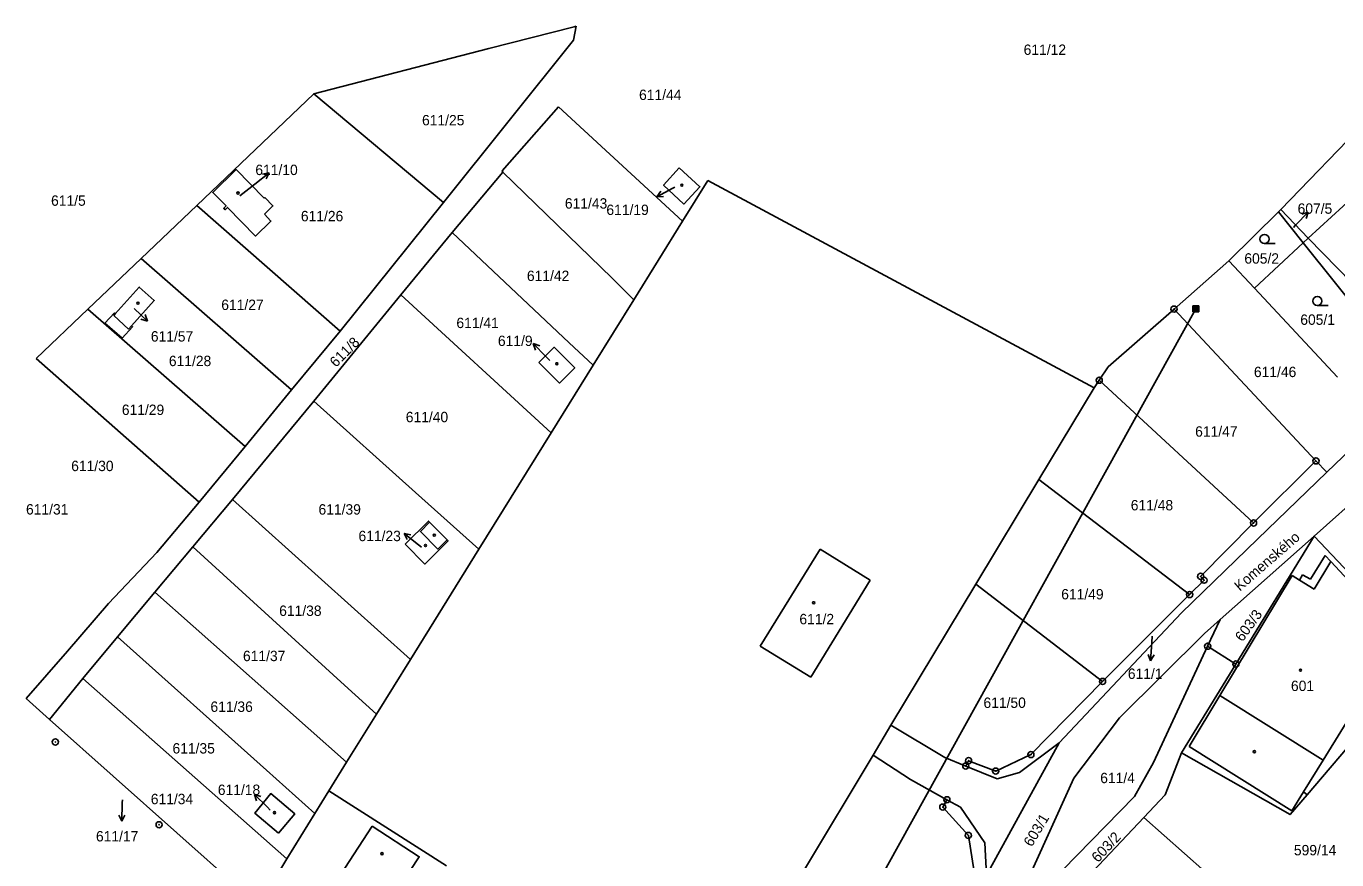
# Model space of a CAD drawing. Extents: x -776701 to -776081, y -974398 to -973771.
# Drawn here: x -776700.9 to -776485.8, y -973908.9 to -973772.2 of the extents above; entities that cross this region are included whole.
import ezdxf

# ---------------------------------------------------------------- set-up
doc = ezdxf.new("R2010")
doc.units = 0
for name, color, linetype in [('Hranice parcel', 7, 'Continuous'), ('Parcelní čísla', 7, 'Continuous'), ('Pop  PČ popisy', 7, 'Continuous'), ('Poz předměty', 7, 'Continuous'), ('Vnitřní kresba', 7, 'Continuous'), ('Značky bodu BP', 7, 'Continuous'), ('Značky budov', 7, 'Continuous'), ('Značky kultur', 7, 'Continuous')]:
    doc.layers.add(name, color=color, linetype=linetype)

msp = doc.modelspace()

# ---------------------------------------------------------------- linework, layer by layer
at = {"layer": 'Hranice parcel'}
for p, q in [((-776624.97, -973775.87), (-776610.98, -973772.28)), ((-776610.98, -973772.28), (-776610.62, -973772.19)), ((-776653.67, -973783.29), (-776624.97, -973775.87)), ((-776672.89, -973801.59), (-776653.67, -973783.29)), ((-776653.67, -973783.29), (-776632.4, -973801.11)), ((-776476.67, -973783.23), (-776495, -973802.25)), ((-776593.17, -973804.15), (-776613.55, -973785.39)), ((-776471.2, -973789.18), (-776490.54, -973806.98)), ((-776630.97, -973806.04), (-776622.69, -973796.12)), ((-776589.04, -973797.5), (-776593.17, -973804.15)), ((-776525.66, -973831.52), (-776589.04, -973797.5)), ((-776682.03, -973810.29), (-776672.89, -973801.59)), ((-776672.89, -973801.59), (-776649.36, -973822.22)), ((-776632.4, -973801.11), (-776649.36, -973822.22)), ((-776495.38, -973802.65), (-776503.53, -973810.68)), ((-776495, -973802.25), (-776495.38, -973802.65)), ((-776491.34, -973807.72), (-776495.38, -973802.65)), ((-776495, -973802.25), (-776490.54, -973806.98)), ((-776639.43, -973816.25), (-776630.97, -973806.04)), ((-776593.17, -973804.15), (-776601.19, -973817.06)), ((-776491.34, -973807.72), (-776499.32, -973815.16)), ((-776490.54, -973806.98), (-776491.34, -973807.72)), ((-776478.83, -973823.4), (-776491.34, -973807.72)), ((-776490.54, -973806.98), (-776476.07, -973821.74)), ((-776690.78, -973818.62), (-776682.03, -973810.29)), ((-776682.03, -973810.29), (-776657.33, -973831.81)), ((-776512.54, -973818.58), (-776503.53, -973810.68)), ((-776503.53, -973810.68), (-776499.32, -973815.16)), ((-776653.69, -973833.69), (-776639.43, -973816.25)), ((-776614.75, -973838.88), (-776639.43, -973816.25)), ((-776499.32, -973815.16), (-776485.7, -973829.75)), ((-776699.26, -973826.69), (-776690.78, -973818.62)), ((-776690.78, -973818.62), (-776664.95, -973841.11)), ((-776601.19, -973817.06), (-776607.86, -973827.79)), ((-776523.35, -973828.07), (-776512.54, -973818.58)), ((-776512.54, -973818.58), (-776489.25, -973843.48)), ((-776649.36, -973822.22), (-776657.33, -973831.81)), ((-776699.26, -973826.69), (-776672.5, -973850.24)), ((-776607.86, -973827.79), (-776614.75, -973838.88)), ((-776524.81, -973830.25), (-776523.35, -973828.07)), ((-776657.33, -973831.81), (-776664.95, -973841.11)), ((-776534.7, -973846.51), (-776525.66, -973831.52)), ((-776525.66, -973831.52), (-776524.81, -973830.25)), ((-776524.81, -973830.25), (-776499.49, -973853.67)), ((-776667.05, -973849.79), (-776653.69, -973833.69)), ((-776478.78, -973836.99), (-776487.44, -973845.34)), ((-776614.75, -973838.88), (-776626.61, -973857.96)), ((-776664.95, -973841.11), (-776672.5, -973850.24)), ((-776489.25, -973843.48), (-776499.49, -973853.67)), ((-776487.44, -973845.34), (-776489.25, -973843.48)), ((-776545.07, -973863.71), (-776534.7, -973846.51)), ((-776534.7, -973846.51), (-776509.98, -973865.41)), ((-776487.44, -973845.34), (-776498.85, -973856.35)), ((-776489.54, -973855.85), (-776477.68, -973845.24)), ((-776672.5, -973850.24), (-776679.43, -973858.51)), ((-776673.56, -973857.58), (-776667.05, -973849.79)), ((-776637.85, -973876.06), (-776667.05, -973849.79)), ((-776679.78, -973865.04), (-776673.56, -973857.58)), ((-776504.98, -973869.51), (-776489.54, -973855.85)), ((-776489.54, -973855.85), (-776502.38, -973876.8)), ((-776679.43, -973858.51), (-776687.36, -973866.87)), ((-776626.61, -973857.96), (-776637.85, -973876.06)), ((-776545.07, -973863.71), (-776524.26, -973879.66)), ((-776685.89, -973872.36), (-776679.78, -973865.04)), ((-776648.32, -973892.9), (-776679.78, -973865.04)), ((-776509.98, -973865.41), (-776524.26, -973879.66)), ((-776687.36, -973866.87), (-776694.11, -973874.71)), ((-776507.02, -973873.88), (-776504.98, -973869.51)), ((-776691.59, -973879.15), (-776685.89, -973872.36)), ((-776694.11, -973874.71), (-776700.88, -973882.48)), ((-776502.38, -973876.8), (-776507.02, -973873.88)), ((-776637.85, -973876.06), (-776643.42, -973885.02)), ((-776502.38, -973876.8), (-776511.33, -973891.39)), ((-776697.06, -973885.88), (-776691.59, -973879.15)), ((-776658.09, -973908.78), (-776691.59, -973879.15)), ((-776700.88, -973882.48), (-776697.06, -973885.88)), ((-776643.42, -973885.02), (-776648.32, -973892.9)), ((-776697.06, -973885.88), (-776665.35, -973914.08)), ((-776531.41, -973889.75), (-776543.29, -973911.41)), ((-776648.32, -973892.9), (-776651.24, -973897.61)), ((-776546.25, -973892.66), (-776546.71, -973893.54)), ((-776651.24, -973897.61), (-776653.51, -973901.3)), ((-776651.24, -973897.61), (-776631.93, -973909.89)), ((-776549.8, -973899.06), (-776550.48, -973900.27)), ((-776653.51, -973901.3), (-776658.09, -973908.78)), ((-776491.84, -973924.62), (-776517.5, -973901.99)), ((-776658.09, -973908.78), (-776661.54, -973914.42))]:
    msp.add_line(p, q, dxfattribs=at)
for points in [[(-776610.62, -973772.19), (-776611.08, -973774.48), (-776632.4, -973801.11)], [(-776622.69, -973796.12), (-776622.77, -973795.9), (-776613.55, -973785.39)], [(-776661.79, -973803.04), (-776660.4, -973801.65), (-776661.74, -973800.3), (-776661.82, -973800.39), (-776666.45, -973795.71), (-776670.26, -973799.45), (-776668.08, -973801.66), (-776668.47, -973802.05), (-776668.23, -973802.29), (-776667.84, -973801.91), (-776663.25, -973806.61), (-776660.73, -973804.15), (-776661.79, -973803.04)], [(-776601.19, -973817.06), (-776604.78, -973813.47), (-776622.69, -973796.12)], [(-776593.73, -973795.4), (-776596.29, -973798.25), (-776592.99, -973801.36), (-776590.33, -973798.53), (-776593.73, -973795.4)], [(-776607.86, -973827.79), (-776611.77, -973824.12), (-776630.97, -973806.04)], [(-776686.26, -973819.36), (-776682.32, -973814.98), (-776679.87, -973817.19), (-776683.59, -973821.32), (-776683.43, -973821.47), (-776685.16, -973823.37), (-776687.97, -973820.91), (-776686.42, -973819.21), (-776686.26, -973819.36)], [(-776616.75, -973827.35), (-776613.36, -973830.72), (-776610.86, -973828.2), (-776614.25, -973824.84), (-776616.75, -973827.35)], [(-776626.61, -973857.96), (-776637, -973848.65), (-776653.69, -973833.69)], [(-776638.71, -973857.17), (-776635.47, -973860.42), (-776631.65, -973856.6), (-776631.82, -973856.43), (-776634.68, -973853.56), (-776634.88, -973853.36), (-776638.71, -973857.17)], [(-776499.49, -973853.67), (-776508.17, -973862.42), (-776507.6, -973863.05), (-776509.98, -973865.41)], [(-776643.42, -973885.02), (-776648.65, -973880.26), (-776673.56, -973857.58)], [(-776498.85, -973856.35), (-776511.31, -973868.4), (-776531.41, -973889.75)], [(-776476.3, -973881.45), (-776471.04, -973875.33), (-776489.54, -973855.85)], [(-776546.71, -973893.54), (-776550.17, -973892.11), (-776559, -973886.81), (-776545.07, -973863.71)], [(-776542.63, -973922.69), (-776536.34, -973911.8), (-776528.99, -973895.55), (-776521.48, -973885.64), (-776507.55, -973871.78), (-776504.98, -973869.51)], [(-776653.51, -973901.3), (-776661.43, -973894.22), (-776685.89, -973872.36)], [(-776507.02, -973873.88), (-776515.9, -973892.93), (-776519.02, -973898.52), (-776542.63, -973922.69)], [(-776524.26, -973879.66), (-776536.02, -973891.66), (-776541.8, -973894.36), (-776546.25, -973892.66)], [(-776490.7, -973898.23), (-776482.79, -973889.01), (-776480.52, -973886.37)], [(-776546.71, -973893.54), (-776541.58, -973895.65), (-776537.9, -973894.58), (-776531.41, -973889.75)], [(-776573.33, -973910.78), (-776561.89, -973891.76), (-776555.79, -973895.76), (-776549.8, -973899.06)], [(-776517.5, -973901.99), (-776513.98, -973898.26), (-776511.33, -973891.39)], [(-776511.33, -973891.39), (-776493.5, -973901.49), (-776490.7, -973898.23)], [(-776659.47, -973904.53), (-776656.81, -973901.4), (-776660.75, -973898.05), (-776663.37, -973901.24), (-776659.47, -973904.53)], [(-776550.48, -973900.27), (-776546.29, -973904.92), (-776545.32, -973910.88), (-776552.01, -973923.68)], [(-776549.8, -973899.06), (-776547.59, -973900.28), (-776543.56, -973906.14), (-776543.29, -973911.41)], [(-776517.5, -973901.99), (-776546.19, -973932.4), (-776552.4, -973941.51), (-776566.6, -973968.35), (-776569.52, -973973.5)], [(-776644.12, -973903.4), (-776636.4, -973908.42), (-776640.94, -973915.31), (-776648.62, -973910.3), (-776644.12, -973903.4)]]:
    msp.add_lwpolyline(points, dxfattribs=at)
at = {"layer": 'Pop  PČ popisy'}
for p, q in [((-776663.36, -973798.07), (-776660.99, -973796.22)), ((-776660.99, -973796.22), (-776662.09, -973796.44)), ((-776660.99, -973796.22), (-776661.48, -973797.23)), ((-776665.83, -973800.01), (-776663.36, -973798.07)), ((-776594.76, -973798.74), (-776597.41, -973800.15)), ((-776597.41, -973800.15), (-776596.76, -973799.24)), ((-776594.47, -973798.58), (-776594.76, -973798.74)), ((-776597.41, -973800.15), (-776596.29, -973800.12)), ((-776492.59, -973804.83), (-776490.51, -973802.67)), ((-776490.51, -973802.67), (-776491.56, -973803.04)), ((-776490.51, -973802.67), (-776490.84, -973803.74)), ((-776492.92, -973805.18), (-776492.59, -973804.83)), ((-776683.17, -973818.5), (-776680.97, -973820.55)), ((-776680.97, -973820.55), (-776682.05, -973820.23)), ((-776680.97, -973820.55), (-776681.37, -973819.5)), ((-776615.58, -973826.41), (-776617.67, -973824.25)), ((-776617.67, -973824.25), (-776616.61, -973824.62)), ((-776617.67, -973824.25), (-776617.33, -973825.32)), ((-776614.98, -973827.04), (-776615.58, -973826.41)), ((-776636.5, -973857.24), (-776638.86, -973855.39)), ((-776638.86, -973855.39), (-776637.77, -973855.61)), ((-776638.86, -973855.39), (-776638.38, -973856.4)), ((-776636, -973857.64), (-776636.5, -973857.24)), ((-776516.1, -973872.23), (-776516.17, -973873.27)), ((-776516.17, -973873.27), (-776516.38, -973876.26)), ((-776516.38, -973876.26), (-776516.81, -973875.23)), ((-776516.38, -973876.26), (-776515.81, -973875.3)), ((-776661.31, -973900.3), (-776663.43, -973898.18)), ((-776663.43, -973898.18), (-776662.37, -973898.53)), ((-776663.43, -973898.18), (-776663.08, -973899.24)), ((-776685.11, -973899.59), (-776685.21, -973902.59)), ((-776685.09, -973899.09), (-776685.11, -973899.59)), ((-776660.85, -973900.76), (-776661.31, -973900.3)), ((-776685.21, -973902.59), (-776685.68, -973901.57)), ((-776685.21, -973902.59), (-776684.68, -973901.61))]:
    msp.add_line(p, q, dxfattribs=at)
at = {"layer": 'Poz předměty'}
for p, q in [((-776508.98, -973818.55), (-776575.4, -973938.41)), ((-776509.48, -973818.05), (-776508.48, -973818.05)), ((-776509.48, -973819.05), (-776509.48, -973818.05)), ((-776509.48, -973818.25), (-776508.48, -973818.25)), ((-776509.48, -973818.45), (-776508.48, -973818.45)), ((-776509.48, -973818.65), (-776508.48, -973818.65)), ((-776509.48, -973818.85), (-776508.48, -973818.85)), ((-776509.28, -973819.05), (-776509.28, -973818.05)), ((-776509.08, -973819.05), (-776509.08, -973818.05)), ((-776508.88, -973819.05), (-776508.88, -973818.05)), ((-776508.68, -973819.05), (-776508.68, -973818.05)), ((-776508.48, -973819.05), (-776508.48, -973818.05)), ((-776509.48, -973819.05), (-776508.48, -973819.05))]:
    msp.add_line(p, q, dxfattribs=at)
at = {"layer": 'Vnitřní kresba'}
for p, q in [((-776686.26, -973819.36), (-776686.52, -973819.65)), ((-776686.52, -973819.65), (-776684.08, -973821.86)), ((-776684.08, -973821.86), (-776683.59, -973821.32)), ((-776570.58, -973857.97), (-776580.43, -973873.87)), ((-776562.38, -973863.05), (-776570.58, -973857.97)), ((-776487.73, -973858.98), (-776490.17, -973862.91)), ((-776486.8, -973860), (-776487.73, -973858.98)), ((-776489.57, -973864.54), (-776486.8, -973860)), ((-776486.8, -973860), (-776472.64, -973875.26)), ((-776572.16, -973878.96), (-776562.38, -973863.05)), ((-776505.02, -973881.97), (-776493.14, -973862.27)), ((-776493.14, -973862.27), (-776491.95, -973863.03)), ((-776491.45, -973862.17), (-776491.95, -973863.03)), ((-776491.95, -973863.03), (-776489.57, -973864.54)), ((-776490.17, -973862.91), (-776491.45, -973862.17)), ((-776580.43, -973873.87), (-776572.16, -973878.96)), ((-776479.85, -973879.22), (-776488.08, -973892.55)), ((-776510.08, -973890.35), (-776505.02, -973881.97)), ((-776488.08, -973892.55), (-776505.02, -973881.97)), ((-776561.89, -973891.76), (-776559, -973886.81)), ((-776493.21, -973900.86), (-776510.08, -973890.35)), ((-776488.08, -973892.55), (-776491.31, -973897.79)), ((-776491.31, -973897.79), (-776493.21, -973900.86)), ((-776491.31, -973897.79), (-776490.7, -973898.23))]:
    msp.add_line(p, q, dxfattribs=at)
msp.add_lwpolyline([(-776634.68, -973853.56), (-776636.2, -973855.08), (-776633.34, -973857.95), (-776631.82, -973856.43)], dxfattribs=at)
at = {"layer": 'Značky bodu BP'}
for centre, radius in [((-776512.54, -973818.58), 0.5), ((-776512.54, -973818.58), 0.0303), ((-776524.81, -973830.25), 0.5), ((-776524.81, -973830.25), 0.0303), ((-776489.25, -973843.48), 0.5), ((-776489.25, -973843.48), 0.0303), ((-776499.49, -973853.67), 0.5), ((-776499.49, -973853.67), 0.0303), ((-776508.17, -973862.42), 0.5), ((-776508.17, -973862.42), 0.0303), ((-776507.6, -973863.05), 0.5), ((-776507.6, -973863.05), 0.0303), ((-776509.98, -973865.41), 0.5), ((-776509.98, -973865.41), 0.0303), ((-776507.02, -973873.88), 0.5), ((-776507.02, -973873.88), 0.0303), ((-776502.38, -973876.8), 0.5), ((-776502.38, -973876.8), 0.0303), ((-776524.26, -973879.66), 0.5), ((-776524.26, -973879.66), 0.0303), ((-776696.1, -973889.59), 0.5), ((-776696.1, -973889.59), 0.0303), ((-776536.02, -973891.66), 0.5), ((-776536.02, -973891.66), 0.0303), ((-776546.71, -973893.54), 0.5), ((-776546.25, -973892.66), 0.5), ((-776546.71, -973893.54), 0.0303), ((-776546.25, -973892.66), 0.0303), ((-776541.8, -973894.36), 0.5), ((-776541.8, -973894.36), 0.0303), ((-776550.48, -973900.27), 0.5), ((-776550.48, -973900.27), 0.0303), ((-776549.8, -973899.06), 0.5), ((-776549.8, -973899.06), 0.0303), ((-776679.07, -973903.16), 0.5), ((-776679.07, -973903.16), 0.0303), ((-776546.29, -973904.92), 0.5), ((-776546.29, -973904.92), 0.0303)]:
    msp.add_circle(centre, radius, dxfattribs=at)
at = {"layer": 'Značky budov'}
for centre in [(-776666.13, -973799.55), (-776593.29, -973798.27), (-776682.54, -973817.62), (-776613.81, -973827.55), (-776633.92, -973855.67), (-776635.36, -973857.37), (-776571.66, -973866.75), (-776491.78, -973877.82), (-776499.36, -973891.17), (-776660.15, -973901.19), (-776642.5, -973907.9)]:
    msp.add_circle(centre, 0.175, dxfattribs=at)
at = {"layer": 'Značky kultur'}
for p, q in [((-776497.7, -973807.85), (-776495.95, -973807.85)), ((-776489.01, -973818.01), (-776487.26, -973818.01))]:
    msp.add_line(p, q, dxfattribs=at)
for centre in [(-776497.7, -973807.1), (-776489.01, -973817.26)]:
    msp.add_circle(centre, 0.75, dxfattribs=at)

# ---------------------------------------------------------------- texts
at = {"layer": 'Parcelní čísla'}
for s, p in [('611/12', (-776537.21, -973776.89)), ('611/44', (-776600.32, -973784.29)), ('611/25', (-776635.93, -973788.45)), ('611/10', (-776663.28, -973796.6)), ('611/5', (-776696.8, -973801.64)), ('611/43', (-776612.49, -973802.1)), ('611/19', (-776605.68, -973803.15)), ('607/5', (-776492.26, -973802.95)), ('611/26', (-776655.81, -973804.18)), ('605/2', (-776501, -973811.13)), ('611/42', (-776618.72, -973813.98)), ('611/27', (-776668.87, -973818.73)), ('611/41', (-776630.29, -973821.7)), ('605/1', (-776491.82, -973821.17)), ('611/57', (-776680.43, -973823.91)), ('611/9', (-776623.48, -973824.64)), ('611/28', (-776677.47, -973827.94)), ('611/46', (-776499.43, -973829.74)), ('611/29', (-776685.19, -973835.95)), ('611/40', (-776638.6, -973837.14)), ('611/47', (-776509.07, -973839.51)), ('611/30', (-776693.5, -973845.16)), ('611/31', (-776700.91, -973852.28)), ('611/39', (-776652.92, -973852.29)), ('611/48', (-776519.64, -973851.6)), ('611/23', (-776646.36, -973856.65)), ('611/49', (-776531.05, -973866.2)), ('611/38', (-776659.37, -973868.91)), ('611/2', (-776574.01, -973870.28)), ('611/37', (-776665.31, -973876.33)), ('611/1', (-776520.12, -973879.24)), ('601', (-776493.35, -973881.23)), ('611/36', (-776670.65, -973884.65)), ('611/50', (-776543.81, -973884)), ('611/35', (-776676.88, -973891.48)), ('611/4', (-776524.65, -973896.34)), ('611/34', (-776680.44, -973899.79)), ('611/18', (-776669.44, -973898.28)), ('611/17', (-776689.43, -973905.9)), ('599/14', (-776492.87, -973908.18))]:
    msp.add_text(s, height=1.7, dxfattribs=at).set_placement(p)
for s, rotation, p in [('611/8', 45, (-776650.06, -973828.23)), ('603/3', 54, (-776501.3, -973873.26)), ('603/1', 59, (-776535.88, -973906.9)), ('603/2', 47, (-776525.01, -973909.47))]:
    msp.add_text(s, height=1.7, rotation=rotation, dxfattribs=at).set_placement(p)
at = {"layer": 'Pop  PČ popisy'}
msp.add_text('Komenského', height=1.7, rotation=41, dxfattribs=at).set_placement((-776501.74, -973864.94))

doc.saveas('drawing.dxf')
